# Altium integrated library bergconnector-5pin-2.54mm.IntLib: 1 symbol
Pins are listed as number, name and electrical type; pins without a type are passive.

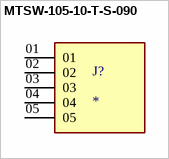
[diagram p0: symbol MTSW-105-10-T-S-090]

## MTSW-105-10-T-S-090
designator J?
MP: MTSW-105-10-T-S-090
footprint SAMTEC_MTSW-105-10-T-S-090
pins: 01, 02, 03, 04, 05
